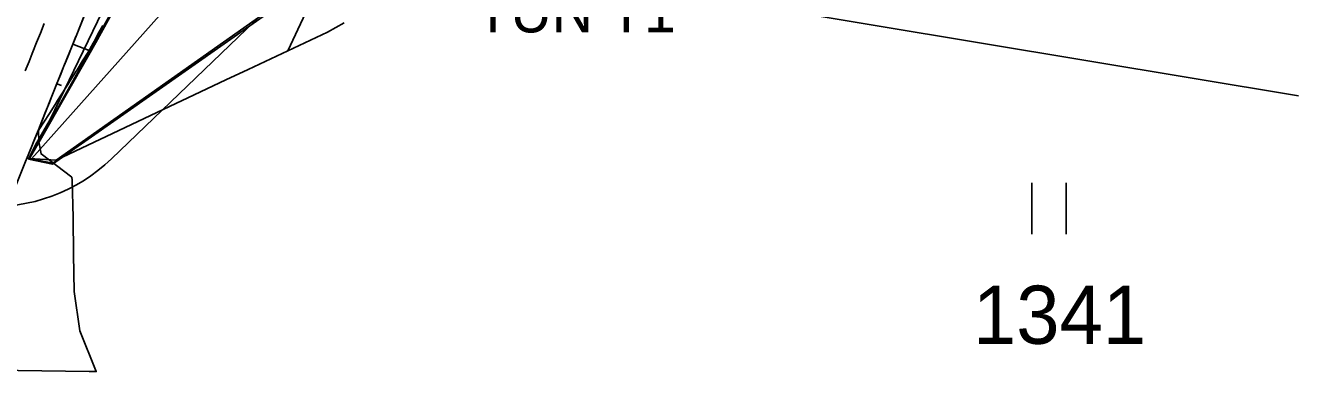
# Model space of a CAD drawing. Extents: x -564037 to -563722, y -1163561 to -1163412.
# Drawn here: x -563977.45 to -563940.26, y -1163507.52 to -1163497.4 of the extents above; entities that cross this region are included whole.
import ezdxf

# ---------------------------------------------------------------- set-up
doc = ezdxf.new("R2010")
doc.units = 0
for name, color, linetype in [('4', 7, 'Continuous'), ('5', 7, 'Continuous'), ('Default', 7, 'Continuous'), ('Line', 7, 'Continuous'), ('Parcelní čísla', 7, 'Continuous'), ('Značky kultur', 7, 'Continuous')]:
    doc.layers.add(name, color=color, linetype=linetype)

msp = doc.modelspace()

# ---------------------------------------------------------------- linework, layer by layer
msp.add_lwpolyline([(-563976.663, -1163501.462), (-563964.742, -1163493.091), (-563961.829, -1163491.15), (-563957.41, -1163486.988), (-563956.735, -1163486.627), (-563953.281, -1163481.221), (-563953.993, -1163478.343), (-563957.796, -1163470.824), (-563957.81, -1163470.439), (-563957.835, -1163469.754), (-563958.239, -1163469.063), (-563958.187, -1163468.683), (-563959.529, -1163466.077), (-563960.166, -1163464.984), (-563964.31, -1163473.527), (-563966.903, -1163478.544), (-563968.406, -1163481.669), (-563970.316, -1163485.955), (-563973.278, -1163492.988), (-563976.735, -1163500.155), (-563977.161, -1163500.889), (-563977.363, -1163501.307)], close=True)
for points in [[(-563940.257, -1163499.457), (-563955.795, -1163496.878), (-563958.985, -1163493.039)], [(-563968.138, -1163497.33), (-563968.634, -1163497.596), (-563970.944, -1163498.688), (-563971.597, -1163498.997), (-563976.56, -1163501.343), (-563977.332, -1163501.295), (-563976.988, -1163500.693), (-563975.559, -1163498.192), (-563975.396, -1163497.906), (-563973.296, -1163494.084)], [(-563977.421, -1163501.309), (-563977.076, -1163500.451), (-563977.017, -1163500.304), (-563976.703, -1163499.524), (-563976.33, -1163498.596), (-563975.956, -1163497.668), (-563975.583, -1163496.741)], [(-563977.823, -1163502.307), (-563977.45, -1163501.379), (-563977.421, -1163501.309), (-563977.309, -1163501.03), (-563977.309, -1163501.029), (-563977.198, -1163500.753), (-563977.087, -1163500.478), (-563977.076, -1163500.451), (-563976.976, -1163500.203), (-563976.865, -1163499.927), (-563976.755, -1163499.652), (-563976.703, -1163499.524), (-563976.644, -1163499.377), (-563976.533, -1163499.101), (-563976.422, -1163498.826), (-563976.33, -1163498.596), (-563976.311, -1163498.551), (-563976.201, -1163498.275), (-563976.09, -1163498), (-563975.979, -1163497.725), (-563975.956, -1163497.668), (-563975.868, -1163497.449), (-563975.757, -1163497.174)], [(-563977.461, -1163498.728), (-563977.35, -1163498.453), (-563977.257, -1163498.223), (-563977.239, -1163498.177), (-563977.128, -1163497.902), (-563977.017, -1163497.627), (-563976.907, -1163497.351)], [(-563977.077, -1163500.482), (-563977.061, -1163500.458), (-563976.914, -1163500.227), (-563976.753, -1163499.973), (-563976.591, -1163499.718), (-563976.516, -1163499.599), (-563976.429, -1163499.463), (-563976.268, -1163499.208), (-563976.107, -1163498.953), (-563975.973, -1163498.74), (-563975.946, -1163498.698), (-563975.785, -1163498.442), (-563975.625, -1163498.187), (-563975.48, -1163497.925), (-563975.451, -1163497.872), (-563975.336, -1163497.663), (-563975.193, -1163497.401)], [(-563977.077, -1163500.482), (-563977.061, -1163500.458), (-563976.914, -1163500.227), (-563976.753, -1163499.973), (-563976.591, -1163499.718), (-563976.516, -1163499.599), (-563976.429, -1163499.463), (-563976.268, -1163499.208), (-563976.107, -1163498.953), (-563975.973, -1163498.74), (-563975.946, -1163498.698), (-563975.785, -1163498.442), (-563975.625, -1163498.187), (-563975.48, -1163497.925), (-563975.451, -1163497.872), (-563975.336, -1163497.663), (-563975.193, -1163497.401)], [(-563979.198, -1163507.467), (-563978.368, -1163507.477), (-563975.597, -1163507.515), (-563975.386, -1163507.517), (-563975.87, -1163506.327), (-563976.036, -1163505.182), (-563976.046, -1163504.1), (-563976.056, -1163503.018), (-563976.088, -1163501.927), (-563976.1, -1163501.84), (-563976.996, -1163501.156), (-563976.997, -1163501.154), (-563977.062, -1163500.808), (-563977.077, -1163500.482)], [(-563979.198, -1163507.467), (-563978.368, -1163507.477), (-563975.597, -1163507.515), (-563975.386, -1163507.517), (-563975.87, -1163506.327), (-563976.036, -1163505.182), (-563976.046, -1163504.1), (-563976.056, -1163503.018), (-563976.088, -1163501.927), (-563976.1, -1163501.84), (-563976.996, -1163501.156), (-563976.997, -1163501.154), (-563977.062, -1163500.808), (-563977.077, -1163500.482)]]:
    msp.add_lwpolyline(points)
at = {"layer": '5'}
msp.add_line((-563974.94, -1163501.303), (-563959.546, -1163486.507), dxfattribs=at)
msp.add_arc((-563978.405, -1163497.698), 5, 218.997, 313.8653, dxfattribs=at)
at = {"layer": 'Default'}
msp.add_lwpolyline([(-563962.482, -1163491.404), (-563976.56, -1163501.343), (-563976.657, -1163501.429), (-563977.332, -1163501.295), (-563974.976, -1163497.082)], dxfattribs=at)
at = {"layer": 'Line'}
for p, q in [((-563962.901, -1163485.181), (-563977.279, -1163501.298)), ((-563967.053, -1163492.285), (-563969.789, -1163498.142)), ((-563967.053, -1163492.285), (-563969.789, -1163498.142)), ((-563976.068, -1163497.947), (-563975.597, -1163498.136)), ((-563976.403, -1163499.159), (-563976.535, -1163499.106))]:
    msp.add_line(p, q, dxfattribs=at)
at = {"layer": 'Značky kultur'}
for p, q in [((-563948.052, -1163503.508), (-563948.052, -1163502.008)), ((-563947.051, -1163503.508), (-563947.051, -1163502.008))]:
    msp.add_line(p, q, dxfattribs=at)

# ---------------------------------------------------------------- texts
at = {"layer": '4'}
msp.add_text('TŮŇ T1', height=1.25, rotation=360, dxfattribs=at).set_placement((-563964.304, -1163497.609))
at = {"layer": 'Parcelní čísla'}
msp.add_text('1341', height=1.7, dxfattribs=at).set_placement((-563949.769, -1163506.708))

doc.saveas('drawing.dxf')
